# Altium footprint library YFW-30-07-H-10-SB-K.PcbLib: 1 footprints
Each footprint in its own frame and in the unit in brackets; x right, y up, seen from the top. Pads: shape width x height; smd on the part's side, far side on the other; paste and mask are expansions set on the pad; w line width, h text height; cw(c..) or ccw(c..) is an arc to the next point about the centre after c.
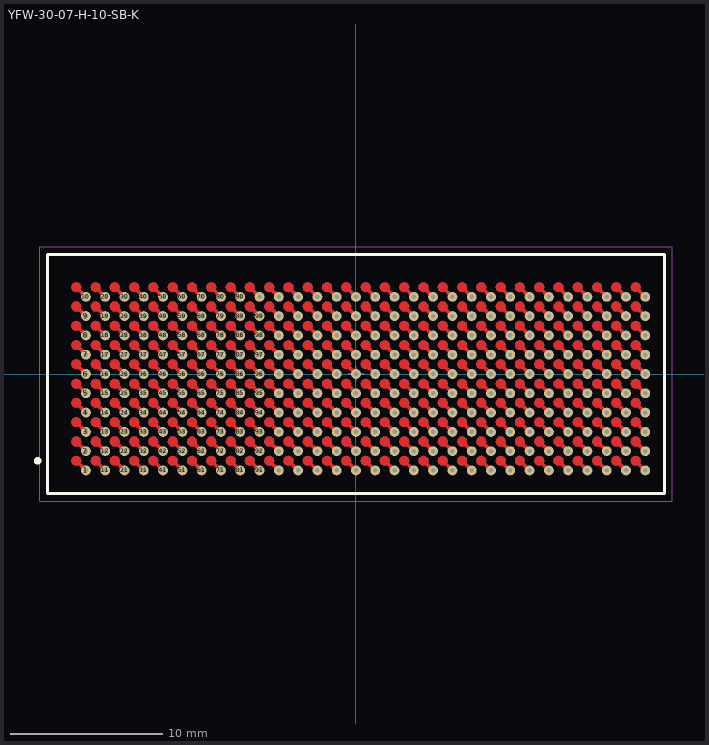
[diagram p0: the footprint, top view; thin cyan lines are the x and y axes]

## YFW-30-07-H-10-SB-K [mm] "1.27mm pitch, 300 pin, high density connector terminal"
height 6.65
pads (300):
  round 0.65 hole 0.3 unplated mask+0: 1(-17.78,-6.35) 2(-17.78,-5.08) 3(-17.78,-3.81) 4(-17.78,-2.54) 5(-17.78,-1.27) 6(-17.78,0) 7(-17.78,1.27) 8(-17.78,2.54) 9(-17.78,3.81) 10(-17.78,5.08) 11(-16.51,-6.35) 12(-16.51,-5.08) 13(-16.51,-3.81) 14(-16.51,-2.54) 15(-16.51,-1.27) 16(-16.51,0) 17(-16.51,1.27) 18(-16.51,2.54) 19(-16.51,3.81) 20(-16.51,5.08) 21(-15.24,-6.35) 22(-15.24,-5.08) 23(-15.24,-3.81) 24(-15.24,-2.54) 25(-15.24,-1.27) 26(-15.24,0) 27(-15.24,1.27) 28(-15.24,2.54) 29(-15.24,3.81) 30(-15.24,5.08) 31(-13.97,-6.35) 32(-13.97,-5.08) 33(-13.97,-3.81) 34(-13.97,-2.54) 35(-13.97,-1.27) 36(-13.97,0) 37(-13.97,1.27) 38(-13.97,2.54) 39(-13.97,3.81) 40(-13.97,5.08) 41(-12.7,-6.35) 42(-12.7,-5.08) 43(-12.7,-3.81) 44(-12.7,-2.54) 45(-12.7,-1.27) 46(-12.7,0) 47(-12.7,1.27) 48(-12.7,2.54) 49(-12.7,3.81) 50(-12.7,5.08) 51(-11.43,-6.35) 52(-11.43,-5.08) 53(-11.43,-3.81) 54(-11.43,-2.54) 55(-11.43,-1.27) 56(-11.43,0) 57(-11.43,1.27) 58(-11.43,2.54) 59(-11.43,3.81) 60(-11.43,5.08) 61(-10.16,-6.35) 62(-10.16,-5.08) 63(-10.16,-3.81) 64(-10.16,-2.54) 65(-10.16,-1.27) 66(-10.16,0) 67(-10.16,1.27) 68(-10.16,2.54) 69(-10.16,3.81) 70(-10.16,5.08) 71(-8.89,-6.35) 72(-8.89,-5.08) 73(-8.89,-3.81) 74(-8.89,-2.54) 75(-8.89,-1.27) 76(-8.89,0) 77(-8.89,1.27) 78(-8.89,2.54) 79(-8.89,3.81) 80(-8.89,5.08) 81(-7.62,-6.35) 82(-7.62,-5.08) 83(-7.62,-3.81) 84(-7.62,-2.54) 85(-7.62,-1.27) 86(-7.62,0) 87(-7.62,1.27) 88(-7.62,2.54) 89(-7.62,3.81) 90(-7.62,5.08) 91(-6.35,-6.35) 92(-6.35,-5.08) 93(-6.35,-3.81) 94(-6.35,-2.54) 95(-6.35,-1.27) 96(-6.35,0) 97(-6.35,1.27) 98(-6.35,2.54) 99(-6.35,3.81) 100(-6.35,5.08) 101(-5.08,-6.35) 102(-5.08,-5.08) 103(-5.08,-3.81) 104(-5.08,-2.54) 105(-5.08,-1.27) 106(-5.08,0) 107(-5.08,1.27) 108(-5.08,2.54) 109(-5.08,3.81) 110(-5.08,5.08) 111(-3.81,-6.35) 112(-3.81,-5.08) 113(-3.81,-3.81) 114(-3.81,-2.54) 115(-3.81,-1.27) 116(-3.81,0) 117(-3.81,1.27) 118(-3.81,2.54) 119(-3.81,3.81) 120(-3.81,5.08) 121(-2.54,-6.35) 122(-2.54,-5.08) 123(-2.54,-3.81) 124(-2.54,-2.54) 125(-2.54,-1.27) 126(-2.54,0) 127(-2.54,1.27) 128(-2.54,2.54) 129(-2.54,3.81) 130(-2.54,5.08) 131(-1.27,-6.35) 132(-1.27,-5.08) 133(-1.27,-3.81) 134(-1.27,-2.54) 135(-1.27,-1.27) 136(-1.27,0) 137(-1.27,1.27) 138(-1.27,2.54) 139(-1.27,3.81) 140(-1.27,5.08) 141(0,-6.35) 142(0,-5.08) 143(0,-3.81) 144(0,-2.54) 145(0,-1.27) 146(0,0) 147(0,1.27) 148(0,2.54) 149(0,3.81) 150(0,5.08) 151(1.27,-6.35) 152(1.27,-5.08) 153(1.27,-3.81) 154(1.27,-2.54) 155(1.27,-1.27) 156(1.27,0) 157(1.27,1.27) 158(1.27,2.54) 159(1.27,3.81) 160(1.27,5.08) 161(2.54,-6.35) 162(2.54,-5.08) 163(2.54,-3.81) 164(2.54,-2.54) 165(2.54,-1.27) 166(2.54,0) 167(2.54,1.27) 168(2.54,2.54) 169(2.54,3.81) 170(2.54,5.08) 171(3.81,-6.35) 172(3.81,-5.08) 173(3.81,-3.81) 174(3.81,-2.54) 175(3.81,-1.27) 176(3.81,0) 177(3.81,1.27) 178(3.81,2.54) 179(3.81,3.81) 180(3.81,5.08) 181(5.08,-6.35) 182(5.08,-5.08) 183(5.08,-3.81) 184(5.08,-2.54) 185(5.08,-1.27) 186(5.08,0) 187(5.08,1.27) 188(5.08,2.54) 189(5.08,3.81) 190(5.08,5.08) 191(6.35,-6.35) 192(6.35,-5.08) 193(6.35,-3.81) 194(6.35,-2.54) 195(6.35,-1.27) 196(6.35,0) 197(6.35,1.27) 198(6.35,2.54) 199(6.35,3.81) 200(6.35,5.08) 201(7.62,-6.35) 202(7.62,-5.08) 203(7.62,-3.81) 204(7.62,-2.54) 205(7.62,-1.27) 206(7.62,0) 207(7.62,1.27) 208(7.62,2.54) 209(7.62,3.81) 210(7.62,5.08) 211(8.89,-6.35) 212(8.89,-5.08) 213(8.89,-3.81) 214(8.89,-2.54) 215(8.89,-1.27) 216(8.89,0) 217(8.89,1.27) 218(8.89,2.54) 219(8.89,3.81) 220(8.89,5.08) 221(10.16,-6.35) 222(10.16,-5.08) 223(10.16,-3.81) 224(10.16,-2.54) 225(10.16,-1.27) 226(10.16,0) 227(10.16,1.27) 228(10.16,2.54) 229(10.16,3.81) 230(10.16,5.08) 231(11.43,-6.35) 232(11.43,-5.08) 233(11.43,-3.81) 234(11.43,-2.54) 235(11.43,-1.27) 236(11.43,0) 237(11.43,1.27) 238(11.43,2.54) 239(11.43,3.81) 240(11.43,5.08) 241(12.7,-6.35) 242(12.7,-5.08) 243(12.7,-3.81) 244(12.7,-2.54) 245(12.7,-1.27) 246(12.7,0) 247(12.7,1.27) 248(12.7,2.54) 249(12.7,3.81) 250(12.7,5.08) 251(13.97,-6.35) 252(13.97,-5.08) 253(13.97,-3.81) 254(13.97,-2.54) 255(13.97,-1.27) 256(13.97,0) 257(13.97,1.27) 258(13.97,2.54) 259(13.97,3.81) 260(13.97,5.08) 261(15.24,-6.35) 262(15.24,-5.08) 263(15.24,-3.81) 264(15.24,-2.54) 265(15.24,-1.27) 266(15.24,0) 267(15.24,1.27) 268(15.24,2.54) 269(15.24,3.81) 270(15.24,5.08) 271(16.51,-6.35) 272(16.51,-5.08) 273(16.51,-3.81) 274(16.51,-2.54) 275(16.51,-1.27) 276(16.51,0) 277(16.51,1.27) 278(16.51,2.54) 279(16.51,3.81) 280(16.51,5.08) 281(17.78,-6.35) 282(17.78,-5.08) 283(17.78,-3.81) 284(17.78,-2.54) 285(17.78,-1.27) 286(17.78,0) 287(17.78,1.27) 288(17.78,2.54) 289(17.78,3.81) 290(17.78,5.08) 291(19.05,-6.35) 292(19.05,-5.08) 293(19.05,-3.81) 294(19.05,-2.54) 295(19.05,-1.27) 296(19.05,0) 297(19.05,1.27) 298(19.05,2.54) 299(19.05,3.81) 300(19.05,5.08)
Top Layer:
  drawing of 600 lines, arcs and shapes, not listed
Top Overlay:
  circle w0.25: c-20.955,-5.715 r0.125
  lines w0.2: -20.32,-7.875 -20.32,7.875 20.32,7.875 20.32,-7.875 -20.32,-7.875
Top Paste:
  drawing of 300 lines, arcs and shapes, not listed
Top Solder:
  drawing of 300 lines, arcs and shapes, not listed
Mechanical 12:
  lines w0.001: -20.32,-7.875 -20.32,7.875 20.32,7.875 20.32,-7.875 -20.32,-7.875
Mechanical 13:
  drawing of 306 lines, arcs and shapes, not listed
  text ".Designator" at 0,0 h1.52
Mechanical 15:
  lines w0.05: -20.82,-8.375 -20.82,8.375 20.82,8.375 20.82,-8.375 -20.82,-8.375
